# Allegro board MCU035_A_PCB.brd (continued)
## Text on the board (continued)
User.8: FIGURE | FINISHED_SIZE | 0.2 | 1.05 | DRILL CHART: TOP to BOTTOM | ALL UNITS ARE IN MILLIMETERS | PLATED | QTY | 795 | 40
